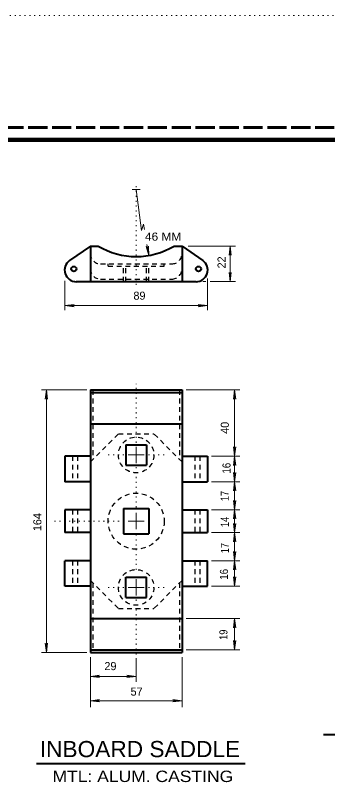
# Model space of a CAD drawing. Extents: x 312583 to 312854, y 144419 to 144597.
# Drawn here: x 312765.5 to 312794.9, y 144524.5 to 144596.8 of the extents above; entities that cross this region are included whole.
import ezdxf
from ezdxf.enums import TextEntityAlignment as Align

# ---------------------------------------------------------------- set-up
doc = ezdxf.new("R2010")
doc.units = 0
doc.header["$LTSCALE"] = 0.3
for name, pattern in [('DOTTED', [1.5, 0.3, -1.2]), ('LONG_DASHED', [7.5, 6, -1.5]), ('SHORT_DASHED', [2.7, 1.5, -1.2])]:
    doc.linetypes.add(name, pattern=pattern)
for name, color, linetype, lineweight in [('1', 7, 'Continuous', 40), ('2', 7, 'Continuous', 13), ('62', 7, 'DOTTED', 13), ('63', 7, 'LONG_DASHED', 60)]:
    doc.layers.add(name, color=color, linetype=linetype, lineweight=lineweight)

msp = doc.modelspace()

# ---------------------------------------------------------------- linework, layer by layer
at = {"layer": '1', "linetype": 'DOTTED', "lineweight": 13}
msp.add_line((312776.8516, 144571.4333), (312776.8516, 144580.7483), dxfattribs=at)
at = {"layer": '1'}
for p, q in [((312772.5429, 144575.0903), (312770.5879, 144573.7256)), ((312772.5429, 144575.0903), (312772.5429, 144571.74)), ((312772.5429, 144575.0903), (312773.2866, 144575.0903)), ((312780.4243, 144575.0903), (312781.1679, 144575.0903)), ((312781.1679, 144575.0903), (312781.1679, 144571.74)), ((312781.1679, 144575.0903), (312783.1153, 144573.7256)), ((312771.2166, 144571.74), (312782.4943, 144571.74)), ((312772.5429, 144561.551), (312781.1679, 144561.551)), ((312772.5429, 144561.551), (312772.5429, 144536.872)), ((312772.5429, 144561.3133), (312781.1679, 144561.3133)), ((312781.1679, 144561.551), (312781.1679, 144536.872)), ((312772.5429, 144558.377), (312781.1679, 144558.377)), ((312775.8933, 144556.399), (312777.8099, 144556.399)), ((312775.8933, 144556.399), (312775.8933, 144554.4823)), ((312777.8099, 144556.399), (312777.8099, 144554.4823)), ((312770.1433, 144555.3256), (312770.1433, 144552.926)), ((312772.5429, 144555.3256), (312770.1433, 144555.3256)), ((312781.1679, 144555.3256), (312783.5599, 144555.3256)), ((312783.5599, 144555.3256), (312783.5599, 144552.926)), ((312775.8933, 144554.4823), (312777.8099, 144554.4823)), ((312772.5429, 144552.926), (312770.1433, 144552.926)), ((312781.1679, 144552.926), (312783.5599, 144552.926)), ((312772.5429, 144550.2886), (312770.1433, 144550.2886)), ((312770.1433, 144550.2886), (312770.1433, 144548.1343)), ((312775.6556, 144550.4113), (312775.6556, 144548.0193)), ((312775.6556, 144550.4113), (312778.0553, 144550.4113)), ((312778.0553, 144550.4113), (312778.0553, 144548.0193)), ((312781.1679, 144550.2886), (312783.5599, 144550.2886)), ((312783.5599, 144550.2886), (312783.5599, 144548.1343)), ((312772.5429, 144548.1343), (312770.1433, 144548.1343)), ((312775.6556, 144548.0193), (312778.0553, 144548.0193)), ((312781.1679, 144548.1343), (312783.5599, 144548.1343)), ((312772.5429, 144545.497), (312770.1433, 144545.497)), ((312770.1433, 144543.105), (312770.1433, 144545.497)), ((312781.1679, 144545.497), (312783.5599, 144545.497)), ((312783.5599, 144543.105), (312783.5599, 144545.497)), ((312775.8933, 144543.9406), (312777.8099, 144543.9406)), ((312775.8933, 144542.024), (312775.8933, 144543.9406)), ((312777.8099, 144542.024), (312777.8099, 144543.9406)), ((312772.5429, 144543.105), (312770.1433, 144543.105)), ((312781.1679, 144543.105), (312783.5599, 144543.105)), ((312775.8933, 144542.024), (312777.8099, 144542.024)), ((312772.5429, 144540.0536), (312781.1679, 144540.0536)), ((312772.5429, 144537.1173), (312781.1679, 144537.1173)), ((312772.5429, 144536.872), (312781.1679, 144536.872))]:
    msp.add_line(p, q, dxfattribs=at)
at = {"layer": '1', "linetype": 'SHORT_DASHED', "lineweight": 25}
for p, q in [((312773.5013, 144573.419), (312780.2096, 144573.419)), ((312774.2143, 144573.1813), (312774.2143, 144573.419)), ((312774.2143, 144573.1813), (312779.4889, 144573.1813)), ((312775.6556, 144571.74), (312775.6556, 144573.1813)), ((312775.8933, 144571.74), (312775.8933, 144573.1813)), ((312777.8099, 144571.74), (312777.8099, 144573.1813)), ((312778.0553, 144571.74), (312778.0553, 144573.1813)), ((312779.4889, 144573.1813), (312779.4889, 144573.419)), ((312773.5013, 144571.9776), (312780.2096, 144571.9776)), ((312772.7806, 144561.551), (312772.7806, 144555.0266)), ((312780.9303, 144561.551), (312780.9303, 144555.019)), ((312772.5429, 144554.7813), (312775.1803, 144557.4186)), ((312775.1803, 144557.4186), (312778.5306, 144557.4186)), ((312781.1679, 144554.7813), (312778.5306, 144557.4186)), ((312770.8639, 144555.3256), (312770.8639, 144552.926)), ((312771.3393, 144555.3256), (312771.3393, 144552.926)), ((312782.3639, 144555.3256), (312782.3639, 144552.926)), ((312782.8469, 144555.3256), (312782.8469, 144552.926)), ((312770.8639, 144550.2886), (312770.8639, 144548.1343)), ((312771.3393, 144550.2886), (312771.3393, 144548.1343)), ((312782.3639, 144550.2886), (312782.3639, 144548.1343)), ((312782.8469, 144550.2886), (312782.8469, 144548.1343)), ((312770.8639, 144545.497), (312770.8639, 144543.105)), ((312771.3393, 144545.497), (312771.3393, 144543.105)), ((312782.3639, 144545.497), (312782.3639, 144543.105)), ((312782.8469, 144545.497), (312782.8469, 144543.105)), ((312772.5429, 144543.6416), (312775.1803, 144541.0043)), ((312781.1679, 144543.6416), (312778.5306, 144541.0043)), ((312772.7806, 144543.404), (312772.7806, 144536.872)), ((312780.9303, 144543.404), (312780.9303, 144536.872)), ((312775.1803, 144541.0043), (312778.5306, 144541.0043))]:
    msp.add_line(p, q, dxfattribs=at)
at = {"layer": '1', "lineweight": 158}
msp.add_lwpolyline([(312616.5, 144423.1446), (312616.5, 144585.0846), (312849, 144585.0846)], dxfattribs=at)
at = {"layer": '1'}
for centre in [(312770.9847, 144572.936), (312782.7185, 144572.936)]:
    msp.add_circle(centre, 0.2396, dxfattribs=at)
at = {"layer": '1', "linetype": 'SHORT_DASHED', "lineweight": 25}
for centre, radius in [((312776.8516, 144555.4406), 1.6771), ((312776.8516, 144549.2115), 2.6354), ((312776.8516, 144542.9823), 1.6771)]:
    msp.add_circle(centre, radius, dxfattribs=at)
at = {"layer": '1'}
for centre, radius, start, end in [((312776.8516, 144581.0511), 6.9479, 239.09046, 300.90954), ((312771.2132, 144572.8286), 1.0925, 124.99202, 270), ((312782.49, 144572.8286), 1.0925, 270, 55.00798)]:
    msp.add_arc(centre, radius, start, end, dxfattribs=at)
at = {"layer": '1', "linetype": 'SHORT_DASHED', "lineweight": 25}
for centre, start, end in [((312773.4974, 144574.3735), 180, 270), ((312780.2058, 144574.3735), 270, 0), ((312773.4974, 144572.936), 180, 270), ((312780.2058, 144572.936), 270, 0)]:
    msp.add_arc(centre, 0.9583, start, end, dxfattribs=at)
at = {"layer": '2'}
for p, q in [((312776.4913, 144580.411), (312777.1506, 144580.411)), ((312777.2196, 144580.411), (312776.5526, 144580.411)), ((312777.5339, 144577.1526), (312777.6259, 144576.6543)), ((312777.7946, 144575.0443), (312777.9479, 144574.7913)), ((312778.0476, 144574.2086), (312777.7946, 144575.0443)), ((312777.8713, 144575.2436), (312778.0476, 144574.2086)), ((312778.0093, 144575.0826), (312777.9479, 144574.7913)), ((312778.0476, 144574.2086), (312778.0093, 144575.0826)), ((312781.7506, 144575.0903), (312786.1973, 144575.0903)), ((312785.6989, 144575.0903), (312785.5916, 144574.224)), ((312785.6989, 144575.0903), (312785.6989, 144571.74)), ((312785.6989, 144575.0903), (312785.8063, 144574.224)), ((312785.5916, 144574.224), (312785.6989, 144574.5)), ((312785.8063, 144574.224), (312785.6989, 144574.5)), ((312785.5916, 144572.6063), (312785.6989, 144572.3303)), ((312785.6989, 144571.74), (312785.5916, 144572.6063)), ((312785.8063, 144572.6063), (312785.6989, 144572.3303)), ((312785.6989, 144571.74), (312785.8063, 144572.6063)), ((312770.1433, 144569.0643), (312770.1433, 144571.8013)), ((312783.1229, 144571.74), (312783.4143, 144571.74)), ((312783.5599, 144569.0643), (312783.5599, 144572.0236)), ((312783.8053, 144571.74), (312786.1973, 144571.74)), ((312770.1433, 144569.4936), (312771.0096, 144569.601)), ((312771.0096, 144569.601), (312770.7336, 144569.4936)), ((312782.6936, 144569.601), (312782.9696, 144569.4936)), ((312783.5599, 144569.4936), (312782.6936, 144569.601)), ((312770.1433, 144569.4936), (312783.5599, 144569.4936)), ((312770.1433, 144569.4936), (312771.0096, 144569.3863)), ((312771.0096, 144569.3863), (312770.7336, 144569.4936)), ((312782.6936, 144569.3863), (312782.9696, 144569.4936)), ((312783.5599, 144569.4936), (312782.6936, 144569.3863)), ((312772.2056, 144561.551), (312767.9276, 144561.551)), ((312768.4106, 144561.551), (312768.3033, 144560.6846)), ((312768.3033, 144560.6846), (312768.4106, 144560.9606)), ((312768.4106, 144561.551), (312768.4106, 144536.872)), ((312768.4106, 144561.551), (312768.5179, 144560.6846)), ((312768.5179, 144560.6846), (312768.4106, 144560.9606)), ((312781.5513, 144561.551), (312786.6189, 144561.551)), ((312786.1129, 144561.551), (312786.0056, 144560.6846)), ((312786.0056, 144560.6846), (312786.1129, 144560.9606)), ((312786.1129, 144555.3256), (312786.1129, 144561.551)), ((312786.1129, 144561.551), (312786.2203, 144560.6846)), ((312786.2203, 144560.6846), (312786.1129, 144560.9606)), ((312776.8516, 144555.4406), (312776.8516, 144556.2073)), ((312786.0056, 144556.192), (312786.1129, 144555.916)), ((312786.1129, 144555.3256), (312786.0056, 144556.192)), ((312786.2203, 144556.192), (312786.1129, 144555.916)), ((312786.1129, 144555.3256), (312786.2203, 144556.192)), ((312776.8516, 144555.4406), (312776.0849, 144555.4406)), ((312776.8516, 144555.4406), (312776.8516, 144554.674)), ((312776.8516, 144555.4406), (312777.6183, 144555.4406)), ((312783.9279, 144555.3256), (312786.6189, 144555.3256)), ((312786.1129, 144555.3256), (312786.0056, 144554.4593)), ((312786.1129, 144552.926), (312786.1129, 144555.3256)), ((312786.1129, 144555.3256), (312786.2203, 144554.4593)), ((312786.0056, 144554.4593), (312786.1129, 144554.7353)), ((312786.2203, 144554.4593), (312786.1129, 144554.7353)), ((312786.0056, 144553.7923), (312786.1129, 144553.5163)), ((312786.1129, 144552.926), (312786.0056, 144553.7923)), ((312786.2203, 144553.7923), (312786.1129, 144553.5163)), ((312786.1129, 144552.926), (312786.2203, 144553.7923)), ((312783.9279, 144552.926), (312786.6189, 144552.926)), ((312786.1129, 144552.926), (312786.0056, 144552.0596)), ((312786.1129, 144550.2886), (312786.1129, 144552.926)), ((312786.1129, 144552.926), (312786.2203, 144552.0596)), ((312786.0056, 144552.0596), (312786.1129, 144552.3356)), ((312786.2203, 144552.0596), (312786.1129, 144552.3356)), ((312786.0056, 144551.155), (312786.1129, 144550.879)), ((312786.1129, 144550.2886), (312786.0056, 144551.155)), ((312786.2203, 144551.155), (312786.1129, 144550.879)), ((312786.1129, 144550.2886), (312786.2203, 144551.155)), ((312783.9279, 144550.2886), (312786.6189, 144550.2886)), ((312786.1129, 144550.2886), (312786.0056, 144549.4223)), ((312786.1129, 144548.1343), (312786.1129, 144550.2886)), ((312786.1129, 144550.2886), (312786.2203, 144549.4223)), ((312776.8516, 144549.2153), (312776.8516, 144549.982)), ((312786.0056, 144549.4223), (312786.1129, 144549.6983)), ((312786.2203, 144549.4223), (312786.1129, 144549.6983)), ((312776.8516, 144549.2153), (312776.0849, 144549.2153)), ((312776.8516, 144549.2153), (312776.8516, 144548.4486)), ((312776.8516, 144549.2153), (312777.6183, 144549.2153)), ((312786.0056, 144549.0006), (312786.1129, 144548.7246)), ((312786.1129, 144548.1343), (312786.0056, 144549.0006)), ((312786.2203, 144549.0006), (312786.1129, 144548.7246)), ((312786.1129, 144548.1343), (312786.2203, 144549.0006)), ((312783.9279, 144548.1343), (312786.6189, 144548.1343)), ((312786.1129, 144548.1343), (312786.0056, 144547.268)), ((312786.1129, 144548.1343), (312786.2203, 144547.268)), ((312786.0056, 144547.268), (312786.1129, 144547.544)), ((312786.2203, 144547.268), (312786.1129, 144547.544)), ((312786.0056, 144546.3633), (312786.1129, 144546.0873)), ((312786.1129, 144545.497), (312786.0056, 144546.3633)), ((312786.2203, 144546.3633), (312786.1129, 144546.0873)), ((312786.1129, 144545.497), (312786.2203, 144546.3633)), ((312783.9279, 144545.497), (312786.6189, 144545.497)), ((312786.1129, 144545.497), (312786.0056, 144544.6306)), ((312786.1129, 144545.497), (312786.2203, 144544.6306)), ((312786.0056, 144544.6306), (312786.1129, 144544.9066)), ((312786.2203, 144544.6306), (312786.1129, 144544.9066)), ((312776.8516, 144542.9823), (312776.8516, 144543.749)), ((312786.0056, 144543.9713), (312786.1129, 144543.6953)), ((312786.1129, 144543.105), (312786.0056, 144543.9713)), ((312786.2203, 144543.9713), (312786.1129, 144543.6953)), ((312786.1129, 144543.105), (312786.2203, 144543.9713)), ((312776.8516, 144542.9823), (312776.0849, 144542.9823)), ((312776.8516, 144542.9823), (312776.8516, 144542.2156)), ((312776.8516, 144542.9823), (312777.6183, 144542.9823)), ((312783.9279, 144543.105), (312786.6189, 144543.105)), ((312781.5436, 144540.0536), (312786.6189, 144540.0536)), ((312786.1129, 144540.0536), (312786.0056, 144539.1873)), ((312786.1129, 144540.0536), (312786.1129, 144537.1173)), ((312786.1129, 144540.0536), (312786.2203, 144539.1873)), ((312786.0056, 144539.1873), (312786.1129, 144539.4633)), ((312786.2203, 144539.1873), (312786.1129, 144539.4633)), ((312786.0056, 144537.9836), (312786.1129, 144537.7076)), ((312786.1129, 144537.1173), (312786.0056, 144537.9836)), ((312786.2203, 144537.9836), (312786.1129, 144537.7076)), ((312786.1129, 144537.1173), (312786.2203, 144537.9836)), ((312768.3033, 144537.7383), (312768.4106, 144537.4623)), ((312768.4106, 144536.872), (312768.3033, 144537.7383)), ((312768.5179, 144537.7383), (312768.4106, 144537.4623)), ((312768.4106, 144536.872), (312768.5179, 144537.7383)), ((312781.5436, 144537.1173), (312786.6189, 144537.1173)), ((312772.2056, 144536.872), (312767.9276, 144536.872)), ((312772.5429, 144536.435), (312772.5429, 144531.72)), ((312776.8516, 144536.3123), (312776.8516, 144534.112)), ((312781.1679, 144536.435), (312781.1679, 144531.72)), ((312772.5429, 144534.618), (312773.4093, 144534.7253)), ((312772.5429, 144534.618), (312776.8516, 144534.618)), ((312772.5429, 144534.618), (312773.4093, 144534.5106)), ((312773.4093, 144534.7253), (312773.1333, 144534.618)), ((312773.4093, 144534.5106), (312773.1333, 144534.618)), ((312775.9853, 144534.7253), (312776.2613, 144534.618)), ((312776.8516, 144534.618), (312775.9853, 144534.7253)), ((312775.9853, 144534.5106), (312776.2613, 144534.618)), ((312776.8516, 144534.618), (312775.9853, 144534.5106)), ((312772.5429, 144532.3256), (312773.4093, 144532.433)), ((312772.5429, 144532.3256), (312781.1679, 144532.3256)), ((312772.5429, 144532.3256), (312773.4093, 144532.2183)), ((312773.4093, 144532.433), (312773.1333, 144532.3256)), ((312773.4093, 144532.2183), (312773.1333, 144532.3256)), ((312780.3016, 144532.433), (312780.5776, 144532.3256)), ((312781.1679, 144532.3256), (312780.3016, 144532.433)), ((312780.3016, 144532.2183), (312780.5776, 144532.3256)), ((312781.1679, 144532.3256), (312780.3016, 144532.2183))]:
    msp.add_line(p, q, dxfattribs=at)
at = {"layer": '2', "linetype": 'DOTTED'}
for p, q in [((312776.8516, 144556.5906), (312776.8516, 144562.1336)), ((312775.7016, 144555.4406), (312774.0073, 144555.4406)), ((312778.0016, 144555.4406), (312779.5809, 144555.4406)), ((312776.8516, 144554.2906), (312776.8516, 144550.4573)), ((312775.7016, 144549.2153), (312769.1159, 144549.2153)), ((312776.8516, 144547.9503), (312776.8516, 144544.3546)), ((312775.7016, 144542.9823), (312774.0916, 144542.9823)), ((312778.0016, 144542.9823), (312779.6653, 144542.9823)), ((312776.8516, 144541.8323), (312776.8516, 144536.3123))]:
    msp.add_line(p, q, dxfattribs=at)
at = {"layer": '2', "lineweight": 40}
for p, q in [((312794.4706, 144529.1402), (312824.235, 144529.1402)), ((312767.4824, 144526.43), (312787.1127, 144526.43))]:
    msp.add_line(p, q, dxfattribs=at)
at = {"layer": '2'}
for points in [[(312776.8516, 144580.411), (312777.3499, 144576.5623), (312777.5339, 144577.1526)], [(312786.1129, 144543.105), (312786.1129, 144545.497), (312786.1129, 144548.1343)]]:
    msp.add_lwpolyline(points, dxfattribs=at)
at = {"layer": '62'}
msp.add_line((312601.2, 144596.7846), (312853.5, 144596.7846), dxfattribs=at)
at = {"layer": '63'}
msp.add_line((312851.75, 144586.2246), (312583.526, 144586.2246), dxfattribs=at)

# ---------------------------------------------------------------- texts
at = {"layer": '2', "width": 1.1}
msp.add_text('46 MM', height=0.76, dxfattribs=at).set_placement((312777.6796, 144575.5953))
at = {"layer": '2'}
for s, p in [('22', (312785.2689, 144572.9856)), ('40', (312785.5761, 144557.4258)), ('164', (312767.9311, 144548.2748))]:
    msp.add_text(s, height=0.76, rotation=90, dxfattribs=at).set_placement(p)
for s, p in [('89', (312776.5992, 144570.0409)), ('29', (312773.8658, 144535.2016)), ('57', (312776.3286, 144532.8058))]:
    msp.add_text(s, height=0.76, dxfattribs=at).set_placement(p)
for s, width, p in [('16', 0.9, (312785.7353, 144553.6867)), ('17', 0.85, (312785.5629, 144551.0997)), ('14', 0.85, (312785.5806, 144548.6543)), ('17', 0.85, (312785.5851, 144546.2006)), ('16', 0.9, (312785.493, 144543.7057)), ('19', 0.85, (312785.4429, 144538.0535))]:
    msp.add_text(s, height=0.76, rotation=90, dxfattribs=dict(at, width=width)).set_placement(p)
for s, height, width, p in [('INBOARD SADDLE', 1.52, 1.05, (312777.2096, 144527.0186)), ('MTL: ALUM. CASTING', 1.07, 1.15, (312777.4826, 144524.6777))]:
    msp.add_text(s, height=height, dxfattribs=dict(at, width=width)).set_placement(p, align=Align.CENTER)

doc.saveas('drawing.dxf')
